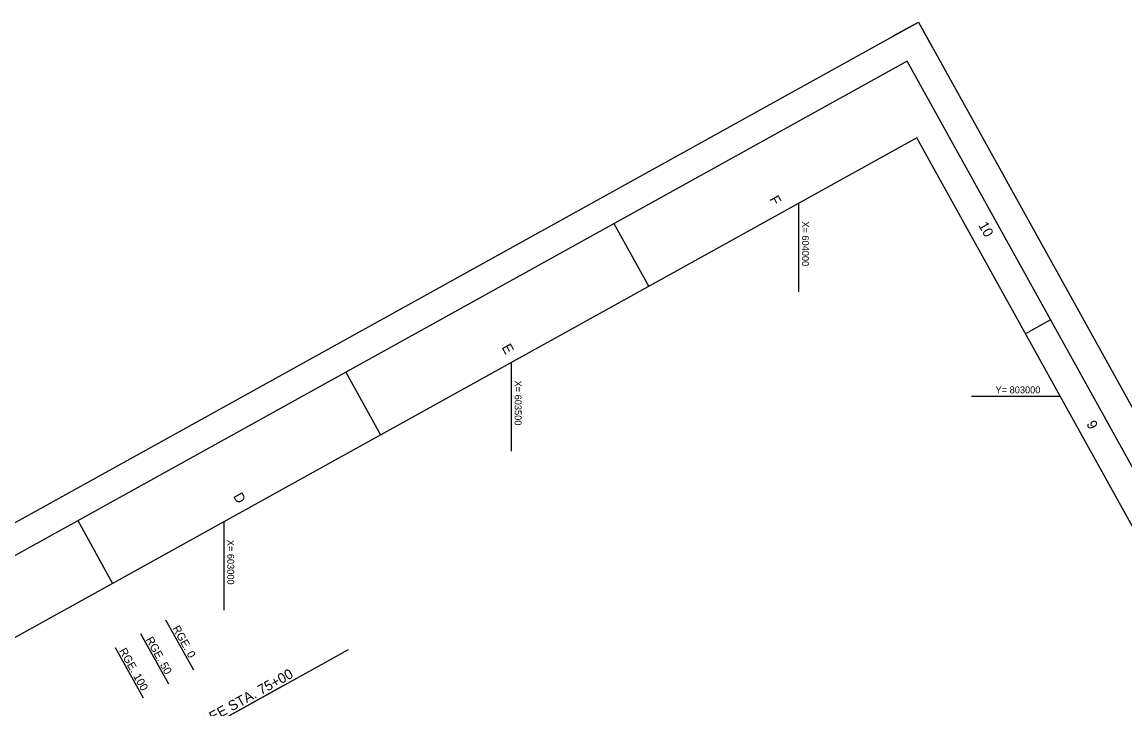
# Model space of a CAD drawing. Extents: x 601234 to 606341, y 798155 to 803651.
# Drawn here: x 602648 to 604567, y 802455 to 803651 of the extents above; entities that cross this region are included whole.
import ezdxf

# ---------------------------------------------------------------- set-up
doc = ezdxf.new("R2010")
doc.units = 0
for name, color, linetype in [('G-ANNO-NPLT', 7, 'Continuous'), ('G-ANNO-TTLB', 7, 'Continuous'), ('V-ALGN-TEXT', 7, 'Continuous'), ('V-ANNO-MATC', 7, 'Continuous'), ('V-ANNO-MATC-IDEN', 7, 'Continuous'), ('V-TOPO-COOR-STAT', 7, 'Continuous')]:
    doc.layers.add(name, color=color, linetype=linetype)

msp = doc.modelspace()

# ---------------------------------------------------------------- linework, layer by layer
at = {"layer": 'G-ANNO-NPLT'}
msp.add_lwpolyline([(604207.8, 803651.4), (606341.2, 799803.3), (603367.7, 798154.7), (601234.2, 802002.9)], close=True, dxfattribs=at)
msp.add_lwpolyline([(604164.1, 803627.2), (604207.8, 803651.4), (604232.1, 803607.7)], dxfattribs=at)
at = {"layer": 'G-ANNO-TTLB'}
for p, q in [((603678, 803300.5), (603738.6, 803191.2)), ((604438, 803133), (604394.3, 803108.8)), ((603211.6, 803041.9), (603272.2, 802932.6)), ((602745.2, 802783.4), (602805.8, 802674))]:
    msp.add_line(p, q, dxfattribs=at)
for points in [[(601302.2, 801983.4), (603387.1, 798222.7), (606273.3, 799822.7), (604188.3, 803583.4)], [(606205.3, 799842.2), (604205.2, 803449.9), (601406.6, 801898.3), (603406.6, 798290.7)]]:
    msp.add_lwpolyline(points, close=True, dxfattribs=at)
at = {"layer": 'V-ALGN-TEXT'}
for p, q in [((602898.1, 802610.9), (602946.6, 802523.4)), ((602854.4, 802586.6), (602902.9, 802499.2)), ((602810.6, 802562.4), (602859.1, 802474.9))]:
    msp.add_line(p, q, dxfattribs=at)
at = {"layer": 'V-ANNO-MATC'}
for p, q in [((603215.9, 802558.4), (602688.1, 802265.8)), ((603104.4, 802496.6), (602798.3, 802326.9))]:
    msp.add_line(p, q, dxfattribs=at)
at = {"layer": 'V-TOPO-COOR-STAT'}
for p, q in [((604000, 803181.7), (604000, 803336.1)), ((603500, 802904.5), (603500, 803058.9)), ((604300.3, 803000), (604454.6, 803000)), ((603000, 802627.3), (603000, 802781.7))]:
    msp.add_line(p, q, dxfattribs=at)

# ---------------------------------------------------------------- texts
at = {"layer": 'G-ANNO-TTLB'}
for s, p in [('F', (603948.2, 803343.4)), ('10', (604311.7, 803297.9)), ('E', (603482.3, 803085.2)), ('9', (604499.6, 802951.8)), ('D', (603015.2, 802826.1))]:
    msp.add_text(s, height=17.5, rotation=299.0039, dxfattribs=at).set_placement(p)
at = {"layer": 'V-ALGN-TEXT'}
for s, p in [('RGE. 0', (602909.5, 802596)), ('RGE. 50', (602863.2, 802576.5)), ('RGE. 100', (602816.8, 802556.9))]:
    msp.add_text(s, height=13.92, rotation=299.0039, dxfattribs=at).set_placement(p)
at = {"layer": 'V-ANNO-MATC-IDEN'}
msp.add_text('MATCHLINE SHEET NO. 021 LEE STA. 75+00', height=17.52, rotation=29.0039, dxfattribs=at).set_placement((602688.5, 802271))
at = {"layer": 'V-TOPO-COOR-STAT'}
for s, p in [('X= 604000', (604005.4, 803304.4)), ('X= 603500', (603505.4, 803027.2)), ('X= 603000', (603005.4, 802750))]:
    msp.add_text(s, height=12, rotation=270, dxfattribs=at).set_placement(p)
msp.add_text('Y= 803000', height=12, dxfattribs=at).set_placement((604342.1, 803005))

doc.saveas('drawing.dxf')
